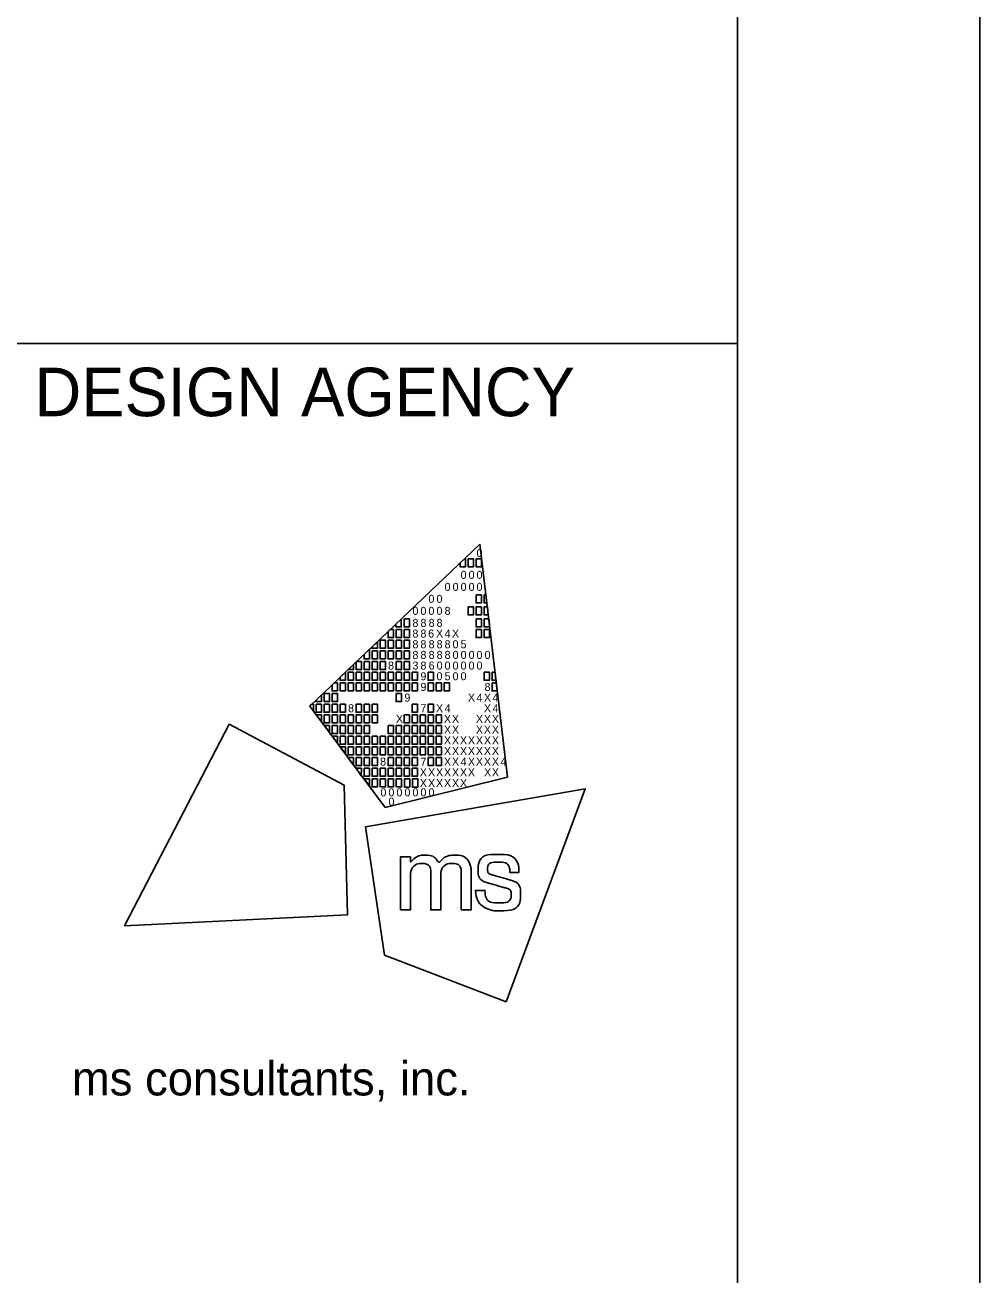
# Model space of a CAD drawing. Extents: x 0 to 34, y 0 to 22.
# Drawn here: x 32.03 to 34, y 2.578 to 5.157 of the extents above; entities that cross this region are included whole.
import ezdxf

# ---------------------------------------------------------------- set-up
doc = ezdxf.new("R2010")
doc.units = 0
for name, color, linetype in [('Default', 7, 'Continuous'), ('SH_Border', 7, 'Continuous'), ('SH_Cut_Line', 7, 'Continuous'), ('SH_Data', 7, 'Continuous')]:
    doc.layers.add(name, color=color, linetype=linetype)

msp = doc.modelspace()

# ---------------------------------------------------------------- linework, layer by layer
at = {"layer": 'Default'}
for p, q in [((32.6176, 3.7519), (32.9688, 4.0861)), ((32.9688, 4.0861), (32.9688, 4.0861)), ((32.9688, 4.0861), (33.0253, 3.6052)), ((32.773, 3.543), (32.6176, 3.7519)), ((33.0253, 3.6052), (32.773, 3.543))]:
    msp.add_line(p, q, dxfattribs=at)
for points in [[(32.9279, 4.0472), (32.9369, 4.0558), (32.939, 4.0558), (32.939, 4.0393), (32.9279, 4.0393)], [(32.9444, 4.0558), (32.9554, 4.0558), (32.9554, 4.0393), (32.9444, 4.0393)], [(32.9609, 4.0558), (32.9719, 4.0558), (32.9719, 4.0393), (32.9609, 4.0393)], [(32.9606, 3.9815), (32.9716, 3.9815), (32.9716, 3.965), (32.9606, 3.965)], [(32.9771, 3.9815), (32.9811, 3.9815), (32.983, 3.965), (32.9771, 3.965)], [(32.9442, 3.9567), (32.9552, 3.9567), (32.9552, 3.9402), (32.9442, 3.9402)], [(32.9606, 3.9567), (32.9716, 3.9567), (32.9716, 3.9402), (32.9606, 3.9402)], [(32.9771, 3.9567), (32.984, 3.9567), (32.9859, 3.9402), (32.9771, 3.9402)], [(32.7954, 3.9211), (32.8064, 3.9316), (32.8064, 3.9154), (32.7954, 3.9154)], [(32.8123, 3.9319), (32.8233, 3.9319), (32.8233, 3.9154), (32.8123, 3.9154)], [(32.9606, 3.9319), (32.9716, 3.9319), (32.9716, 3.9154), (32.9606, 3.9154)], [(32.9771, 3.9319), (32.9869, 3.9319), (32.9881, 3.9218), (32.9881, 3.9154), (32.9771, 3.9154)], [(32.7958, 3.9099), (32.8068, 3.9099), (32.8068, 3.8934), (32.7958, 3.8934)], [(32.8123, 3.9099), (32.8233, 3.9099), (32.8233, 3.8934), (32.8123, 3.8934)], [(32.9606, 3.9099), (32.9716, 3.9099), (32.9716, 3.8934), (32.9606, 3.8934)], [(32.9771, 3.9099), (32.9881, 3.9099), (32.9881, 3.8934), (32.9771, 3.8934)], [(32.7628, 3.8879), (32.7738, 3.8879), (32.7738, 3.8714), (32.7628, 3.8714)], [(32.7793, 3.8879), (32.7903, 3.8879), (32.7903, 3.8714), (32.7793, 3.8714)], [(32.7958, 3.8879), (32.8068, 3.8879), (32.8068, 3.8714), (32.7958, 3.8714)], [(32.8123, 3.8879), (32.8233, 3.8879), (32.8233, 3.8714), (32.8123, 3.8714)], [(32.7297, 3.8439), (32.7407, 3.8439), (32.7407, 3.8273), (32.7297, 3.8273)], [(32.7463, 3.8659), (32.7573, 3.8659), (32.7573, 3.8494), (32.7463, 3.8494)], [(32.7463, 3.8439), (32.7573, 3.8439), (32.7573, 3.8273), (32.7463, 3.8273)], [(32.7628, 3.8659), (32.7738, 3.8659), (32.7738, 3.8494), (32.7628, 3.8494)], [(32.7628, 3.8439), (32.7738, 3.8439), (32.7738, 3.8273), (32.7628, 3.8273)], [(32.7793, 3.8659), (32.7903, 3.8659), (32.7903, 3.8494), (32.7793, 3.8494)], [(32.7958, 3.8659), (32.8068, 3.8659), (32.8068, 3.8494), (32.7958, 3.8494)], [(32.7958, 3.8439), (32.8068, 3.8439), (32.8068, 3.8273), (32.7958, 3.8273)], [(32.8123, 3.8659), (32.8233, 3.8659), (32.8233, 3.8494), (32.8123, 3.8494)], [(32.8123, 3.8439), (32.8233, 3.8439), (32.8233, 3.8273), (32.8123, 3.8273)], [(32.6967, 3.8218), (32.7077, 3.8218), (32.7077, 3.8053), (32.6967, 3.8053)], [(32.7132, 3.8218), (32.7242, 3.8218), (32.7242, 3.8053), (32.7132, 3.8053)], [(32.7297, 3.8218), (32.7407, 3.8218), (32.7407, 3.8053), (32.7297, 3.8053)], [(32.7463, 3.8218), (32.7573, 3.8218), (32.7573, 3.8053), (32.7463, 3.8053)], [(32.7628, 3.8218), (32.7738, 3.8218), (32.7738, 3.8053), (32.7628, 3.8053)], [(32.7793, 3.8218), (32.7903, 3.8218), (32.7903, 3.8053), (32.7793, 3.8053)], [(32.7958, 3.8218), (32.8068, 3.8218), (32.8068, 3.8053), (32.7958, 3.8053)], [(32.8123, 3.8218), (32.8233, 3.8218), (32.8233, 3.8053), (32.8123, 3.8053)], [(32.8288, 3.8218), (32.8398, 3.8218), (32.8398, 3.8053), (32.8288, 3.8053)], [(32.8618, 3.8218), (32.8729, 3.8218), (32.8729, 3.8053), (32.8618, 3.8053)], [(32.9771, 3.8218), (32.9881, 3.8218), (32.9881, 3.8053), (32.9771, 3.8053)], [(32.9936, 3.8218), (32.9999, 3.8218), (33.0018, 3.8053), (32.9936, 3.8053)], [(32.6802, 3.7998), (32.6912, 3.7998), (32.6912, 3.7833), (32.6802, 3.7833)], [(32.6967, 3.7998), (32.7077, 3.7998), (32.7077, 3.7833), (32.6967, 3.7833)], [(32.7132, 3.7998), (32.7242, 3.7998), (32.7242, 3.7833), (32.7132, 3.7833)], [(32.7297, 3.7998), (32.7407, 3.7998), (32.7407, 3.7833), (32.7297, 3.7833)], [(32.7463, 3.7998), (32.7573, 3.7998), (32.7573, 3.7833), (32.7463, 3.7833)], [(32.7628, 3.7998), (32.7738, 3.7998), (32.7738, 3.7833), (32.7628, 3.7833)], [(32.7793, 3.7998), (32.7903, 3.7998), (32.7903, 3.7833), (32.7793, 3.7833)], [(32.7958, 3.7998), (32.8068, 3.7998), (32.8068, 3.7833), (32.7958, 3.7833)], [(32.8123, 3.7998), (32.8233, 3.7998), (32.8233, 3.7833), (32.8123, 3.7833)], [(32.8288, 3.7998), (32.8398, 3.7998), (32.8398, 3.7833), (32.8288, 3.7833)], [(32.8618, 3.7998), (32.8729, 3.7998), (32.8729, 3.7833), (32.8618, 3.7833)], [(32.8784, 3.7998), (32.8894, 3.7998), (32.8894, 3.7833), (32.8784, 3.7833)], [(32.8947, 3.7998), (32.9057, 3.7998), (32.9057, 3.7833), (32.8947, 3.7833)], [(32.9936, 3.7998), (33.0024, 3.7998), (33.0044, 3.7833), (32.9936, 3.7833)], [(32.6472, 3.7778), (32.6582, 3.7778), (32.6582, 3.7613), (32.6472, 3.7613)], [(32.6637, 3.7778), (32.6747, 3.7778), (32.6747, 3.7613), (32.6637, 3.7613)], [(32.7958, 3.7778), (32.8068, 3.7778), (32.8068, 3.7613), (32.7958, 3.7613)], [(32.6307, 3.7558), (32.6417, 3.7558), (32.6417, 3.7393), (32.6307, 3.7393)], [(32.6472, 3.7558), (32.6582, 3.7558), (32.6582, 3.7393), (32.6472, 3.7393)], [(32.6637, 3.7558), (32.6747, 3.7558), (32.6747, 3.7393), (32.6637, 3.7393)], [(32.6802, 3.7558), (32.6912, 3.7558), (32.6912, 3.7393), (32.6802, 3.7393)], [(32.7132, 3.7558), (32.7242, 3.7558), (32.7242, 3.7393), (32.7132, 3.7393)], [(32.7297, 3.7558), (32.7407, 3.7558), (32.7407, 3.7393), (32.7297, 3.7393)], [(32.7463, 3.7558), (32.7573, 3.7558), (32.7573, 3.7393), (32.7463, 3.7393)], [(32.8288, 3.7558), (32.8398, 3.7558), (32.8398, 3.7393), (32.8288, 3.7393)], [(32.8618, 3.7558), (32.8729, 3.7558), (32.8729, 3.7393), (32.8618, 3.7393)], [(32.6307, 3.7338), (32.6417, 3.7338), (32.6417, 3.72)], [(32.6472, 3.7338), (32.6582, 3.7338), (32.6582, 3.7173), (32.6472, 3.7173)], [(32.6637, 3.7338), (32.6747, 3.7338), (32.6747, 3.7173), (32.6637, 3.7173)], [(32.6802, 3.7338), (32.6912, 3.7338), (32.6912, 3.7173), (32.6802, 3.7173)], [(32.6967, 3.7338), (32.7077, 3.7338), (32.7077, 3.7173), (32.6967, 3.7173)], [(32.7132, 3.7338), (32.7242, 3.7338), (32.7242, 3.7173), (32.7132, 3.7173)], [(32.7297, 3.7338), (32.7407, 3.7338), (32.7407, 3.7173), (32.7297, 3.7173)], [(32.7463, 3.7338), (32.7573, 3.7338), (32.7573, 3.7173), (32.7463, 3.7173)], [(32.8123, 3.7338), (32.8233, 3.7338), (32.8233, 3.7173), (32.8123, 3.7173)], [(32.8288, 3.7338), (32.8398, 3.7338), (32.8398, 3.7173), (32.8288, 3.7173)], [(32.8453, 3.7338), (32.8563, 3.7338), (32.8563, 3.7173), (32.8453, 3.7173)], [(32.8618, 3.7338), (32.8729, 3.7338), (32.8729, 3.7173), (32.8618, 3.7173)], [(32.8784, 3.7338), (32.8894, 3.7338), (32.8894, 3.7173), (32.8784, 3.7173)], [(32.6472, 3.7117), (32.6582, 3.7117), (32.6582, 3.698)], [(32.6637, 3.7117), (32.6747, 3.7117), (32.6747, 3.6952), (32.6637, 3.6952)], [(32.6637, 3.6897), (32.6747, 3.6897), (32.6747, 3.676)], [(32.6747, 3.6897), (32.6747, 3.6897), (32.6747, 3.6897)], [(32.6802, 3.7117), (32.6912, 3.7117), (32.6912, 3.6952), (32.6802, 3.6952)], [(32.6802, 3.6897), (32.6912, 3.6897), (32.6912, 3.6732), (32.6802, 3.6732)], [(32.6967, 3.7117), (32.7077, 3.7117), (32.7077, 3.6952), (32.6967, 3.6952)], [(32.6967, 3.6897), (32.7077, 3.6897), (32.7077, 3.6732), (32.6967, 3.6732)], [(32.7132, 3.7117), (32.7242, 3.7117), (32.7242, 3.6952), (32.7132, 3.6952)], [(32.7132, 3.6897), (32.7242, 3.6897), (32.7242, 3.6732), (32.7132, 3.6732)], [(32.7297, 3.7117), (32.7407, 3.7117), (32.7407, 3.6952), (32.7297, 3.6952)], [(32.7297, 3.6897), (32.7407, 3.6897), (32.7407, 3.6732), (32.7297, 3.6732)], [(32.7463, 3.6897), (32.7573, 3.6897), (32.7573, 3.6732), (32.7463, 3.6732)], [(32.7628, 3.6897), (32.7738, 3.6897), (32.7738, 3.6732), (32.7628, 3.6732)], [(32.7793, 3.7117), (32.7903, 3.7117), (32.7903, 3.6952), (32.7793, 3.6952)], [(32.7793, 3.6897), (32.7903, 3.6897), (32.7903, 3.6732), (32.7793, 3.6732)], [(32.7958, 3.7117), (32.8068, 3.7117), (32.8068, 3.6952), (32.7958, 3.6952)], [(32.7958, 3.6897), (32.8068, 3.6897), (32.8068, 3.6732), (32.7958, 3.6732)], [(32.8123, 3.7117), (32.8233, 3.7117), (32.8233, 3.6952), (32.8123, 3.6952)], [(32.8123, 3.6897), (32.8233, 3.6897), (32.8233, 3.6732), (32.8123, 3.6732)], [(32.8288, 3.7117), (32.8398, 3.7117), (32.8398, 3.6952), (32.8288, 3.6952)], [(32.8288, 3.6897), (32.8398, 3.6897), (32.8398, 3.6732), (32.8288, 3.6732)], [(32.8453, 3.7117), (32.8563, 3.7117), (32.8563, 3.6952), (32.8453, 3.6952)], [(32.8453, 3.6897), (32.8563, 3.6897), (32.8563, 3.6732), (32.8453, 3.6732)], [(32.8618, 3.7117), (32.8729, 3.7117), (32.8729, 3.6952), (32.8618, 3.6952)], [(32.8618, 3.6897), (32.8729, 3.6897), (32.8729, 3.6732), (32.8618, 3.6732)], [(32.8784, 3.7117), (32.8894, 3.7117), (32.8894, 3.6952), (32.8784, 3.6952)], [(32.8784, 3.6897), (32.8894, 3.6897), (32.8894, 3.6732), (32.8784, 3.6732)], [(32.6802, 3.6677), (32.6912, 3.6677), (32.6912, 3.654)], [(32.6967, 3.6677), (32.7077, 3.6677), (32.7077, 3.6512), (32.6967, 3.6512)], [(32.7132, 3.6677), (32.7242, 3.6677), (32.7242, 3.6512), (32.7132, 3.6512)], [(32.7297, 3.6677), (32.7407, 3.6677), (32.7407, 3.6512), (32.7297, 3.6512)], [(32.7463, 3.6677), (32.7573, 3.6677), (32.7573, 3.6512), (32.7463, 3.6512)], [(32.7628, 3.6677), (32.7738, 3.6677), (32.7738, 3.6512), (32.7628, 3.6512)], [(32.7793, 3.6677), (32.7903, 3.6677), (32.7903, 3.6512), (32.7793, 3.6512)], [(32.7958, 3.6677), (32.8068, 3.6677), (32.8068, 3.6512), (32.7958, 3.6512)], [(32.8123, 3.6677), (32.8233, 3.6677), (32.8233, 3.6512), (32.8123, 3.6512)], [(32.8288, 3.6677), (32.8398, 3.6677), (32.8398, 3.6512), (32.8288, 3.6512)], [(32.8453, 3.6677), (32.8563, 3.6677), (32.8563, 3.6512), (32.8453, 3.6512)], [(32.8618, 3.6677), (32.8729, 3.6677), (32.8729, 3.6512), (32.8618, 3.6512)], [(32.8784, 3.6677), (32.8894, 3.6677), (32.8894, 3.6512), (32.8784, 3.6512)], [(32.7078, 3.6305), (32.6966, 3.6457), (32.7078, 3.6457)], [(32.7132, 3.6457), (32.7242, 3.6457), (32.7242, 3.6292), (32.7132, 3.6292)], [(32.7297, 3.6457), (32.7407, 3.6457), (32.7407, 3.6292), (32.7297, 3.6292)], [(32.7463, 3.6457), (32.7573, 3.6457), (32.7573, 3.6292), (32.7463, 3.6292)], [(32.7793, 3.6457), (32.7903, 3.6457), (32.7903, 3.6292), (32.7793, 3.6292)], [(32.7958, 3.6457), (32.8068, 3.6457), (32.8068, 3.6292), (32.7958, 3.6292)], [(32.8123, 3.6457), (32.8233, 3.6457), (32.8233, 3.6292), (32.8123, 3.6292)], [(32.8288, 3.6457), (32.8398, 3.6457), (32.8398, 3.6292), (32.8288, 3.6292)], [(32.8618, 3.6457), (32.8729, 3.6457), (32.8729, 3.6292), (32.8618, 3.6292)], [(32.8784, 3.6457), (32.8894, 3.6457), (32.8894, 3.6292), (32.8784, 3.6292)], [(32.724, 3.6082), (32.7132, 3.6237), (32.7242, 3.6237)], [(32.7297, 3.6237), (32.7407, 3.6237), (32.7407, 3.6072), (32.7297, 3.6072)], [(32.7463, 3.6237), (32.7573, 3.6237), (32.7573, 3.6072), (32.7463, 3.6072)], [(32.7628, 3.6237), (32.7738, 3.6237), (32.7738, 3.6072), (32.7628, 3.6072)], [(32.7793, 3.6237), (32.7903, 3.6237), (32.7903, 3.6072), (32.7793, 3.6072)], [(32.7958, 3.6237), (32.8068, 3.6237), (32.8068, 3.6072), (32.7958, 3.6072)], [(32.8123, 3.6237), (32.8233, 3.6237), (32.8233, 3.6072), (32.8123, 3.6072)], [(32.8288, 3.6237), (32.8398, 3.6237), (32.8398, 3.6072), (32.8288, 3.6072)], [(32.7302, 3.6017), (32.7407, 3.6017), (32.7408, 3.5875)], [(32.7463, 3.6017), (32.7573, 3.6017), (32.7573, 3.5852), (32.7463, 3.5852)], [(32.763, 3.6017), (32.774, 3.6017), (32.774, 3.5852), (32.763, 3.5852)], [(32.7794, 3.6017), (32.7904, 3.6017), (32.7904, 3.5852), (32.7794, 3.5852)], [(32.7961, 3.6017), (32.8071, 3.6017), (32.8071, 3.5852), (32.7961, 3.5852)], [(32.813, 3.6017), (32.824, 3.6017), (32.824, 3.5851), (32.813, 3.5851)], [(32.8296, 3.6017), (32.8407, 3.6017), (32.8407, 3.5851), (32.8296, 3.5851)]]:
    msp.add_lwpolyline(points, close=True, dxfattribs=at)
for points in [[(32.7903, 3.9099), (32.7836, 3.9099), (32.7793, 3.9058), (32.7793, 3.8934), (32.7903, 3.8934), (32.7903, 3.9099)], [(32.7407, 3.8691), (32.7297, 3.8587), (32.7297, 3.8494), (32.7407, 3.8494), (32.7407, 3.8691)], [(32.7573, 3.8849), (32.7463, 3.8744), (32.7463, 3.8714), (32.7573, 3.8714), (32.7573, 3.8849)], [(32.7242, 3.8439), (32.7142, 3.8439), (32.7132, 3.843), (32.7132, 3.8273), (32.7242, 3.8273), (32.7242, 3.8439)], [(32.6912, 3.822), (32.6802, 3.8115), (32.6802, 3.8053), (32.6912, 3.8053), (32.6912, 3.822)], [(32.7077, 3.8377), (32.6968, 3.8273), (32.7077, 3.8273), (32.7077, 3.8377)], [(32.6747, 3.7998), (32.6679, 3.7998), (32.6637, 3.7958), (32.6637, 3.7833), (32.6747, 3.7833), (32.6747, 3.7998)], [(32.6417, 3.7749), (32.6307, 3.7644), (32.6307, 3.7613), (32.6417, 3.7613), (32.6417, 3.7749)], [(32.6252, 3.7558), (32.6216, 3.7558), (32.6176, 3.7519), (32.6252, 3.7417), (32.6252, 3.7558)], [(32.4512, 3.7149), (32.2359, 3.2988), (32.6957, 3.3215), (32.6884, 3.5892), (32.4512, 3.7149)], [(33.0229, 3.1422), (33.1859, 3.5814), (32.7324, 3.5029), (32.7722, 3.2381), (33.0229, 3.1422)]]:
    msp.add_lwpolyline(points, dxfattribs=at)
for points in [[(32.8048, 3.3315), (32.8048, 3.3315), (32.8048, 3.4409), (32.8048, 3.4409), (32.8048, 3.4409), (32.8255, 3.4409), (32.8255, 3.4409), (32.8255, 3.4409), (32.8255, 3.4297), (32.8255, 3.4297), (32.8346, 3.4399), (32.8457, 3.4445), (32.8555, 3.4445), (32.8689, 3.4445), (32.8792, 3.4372), (32.8837, 3.4266), (32.8915, 3.4381), (32.905, 3.4446), (32.9166, 3.4446), (32.9325, 3.4446), (32.9451, 3.435), (32.9494, 3.4213), (32.9494, 3.4212), (32.9494, 3.4212), (32.9495, 3.4212), (32.9501, 3.419), (32.9507, 3.4172), (32.9507, 3.4071), (32.9507, 3.4071), (32.9507, 3.3314), (32.9507, 3.3314), (32.9507, 3.3314), (32.9303, 3.3314), (32.9303, 3.3314), (32.9303, 3.3314), (32.9303, 3.4048), (32.9303, 3.4048), (32.9303, 3.4201), (32.9219, 3.4274), (32.9111, 3.4274), (32.8995, 3.4274), (32.888, 3.4171), (32.888, 3.4001), (32.888, 3.4001), (32.888, 3.3315), (32.888, 3.3315), (32.888, 3.3315), (32.8674, 3.3315), (32.8674, 3.3315), (32.8674, 3.3315), (32.8674, 3.4059), (32.8674, 3.4059), (32.8674, 3.4203), (32.8588, 3.4274), (32.8497, 3.4274), (32.8384, 3.4274), (32.8254, 3.417), (32.8254, 3.3962), (32.8254, 3.3962), (32.8254, 3.3315), (32.8254, 3.3315), (32.8254, 3.3315), (32.8048, 3.3315), (32.8048, 3.3315)], [(32.9596, 3.3709), (32.9596, 3.3709), (32.9595, 3.3717), (32.9595, 3.3717), (32.9595, 3.3717), (32.9603, 3.3717), (32.9603, 3.3717), (32.9603, 3.3717), (32.9783, 3.3717), (32.9783, 3.3717), (32.9783, 3.3717), (32.9789, 3.3717), (32.9789, 3.3717), (32.9789, 3.3717), (32.979, 3.371), (32.979, 3.371), (32.9803, 3.3554), (32.9887, 3.346), (33.009, 3.346), (33.0273, 3.346), (33.0333, 3.3554), (33.0333, 3.3631), (33.0333, 3.3732), (33.0256, 3.3758), (33.0175, 3.378), (33.0175, 3.378), (32.987, 3.3867), (32.987, 3.3867), (32.9721, 3.3909), (32.9648, 3.4019), (32.9648, 3.4142), (32.9648, 3.4303), (32.9768, 3.4462), (33.0052, 3.4462), (33.0348, 3.4462), (33.0489, 3.4285), (33.0489, 3.4095), (33.0489, 3.4095), (33.0489, 3.4087), (33.0489, 3.4087), (33.0489, 3.4087), (33.0482, 3.4087), (33.0482, 3.4087), (33.0482, 3.4087), (33.0312, 3.4087), (33.0312, 3.4087), (33.0312, 3.4087), (33.0305, 3.4087), (33.0305, 3.4087), (33.0305, 3.4087), (33.0305, 3.4094), (33.0305, 3.4094), (33.0302, 3.4208), (33.0227, 3.43), (33.0056, 3.43), (32.9891, 3.43), (32.9843, 3.4218), (32.9843, 3.4157), (32.9843, 3.4108), (32.9869, 3.4059), (32.9959, 3.4033), (32.9959, 3.4033), (33.0255, 3.3948), (33.0255, 3.3948), (33.0462, 3.3889), (33.0527, 3.3777), (33.0527, 3.3639), (33.0527, 3.3462), (33.041, 3.3298), (33.0087, 3.3298), (32.9952, 3.3298), (32.9877, 3.3321), (32.9823, 3.3348), (32.9691, 3.3414), (32.961, 3.3536), (32.9596, 3.3709)]]:
    msp.add_open_spline(points, degree=3, dxfattribs=at)
at = {"layer": 'SH_Border'}
msp.add_line((32, 4.5), (33.5, 4.5), dxfattribs=at)
msp.add_lwpolyline([(1.5, 21.5), (33.5, 21.5), (33.5, 0.5), (1.5, 0.5)], close=True, dxfattribs=at)
at = {"layer": 'SH_Cut_Line'}
msp.add_lwpolyline([(0, 0), (34, 0), (34, 22), (0, 22)], close=True, dxfattribs=at)
at = {"layer": 'SH_Data'}
msp.add_line((32.75, 3.5), (32.75, 3.5), dxfattribs=at)

# ---------------------------------------------------------------- texts
at = {"layer": 'Default'}
for s, p in [('0', (32.9617, 4.0597)), ('0', (32.9288, 4.0145)), ('0', (32.9453, 4.0145)), ('0', (32.9617, 4.0145)), ('0', (32.8958, 3.9897)), ('0', (32.9123, 3.9897)), ('0', (32.9288, 3.9897)), ('0', (32.9453, 3.9897)), ('0', (32.9617, 3.9897)), ('0', (32.8625, 3.965)), ('0', (32.8791, 3.965)), ('0', (32.8295, 3.9402)), ('0', (32.846, 3.9402)), ('0', (32.8625, 3.9402)), ('0', (32.8791, 3.9402)), ('8', (32.8958, 3.9402)), ('8', (32.8295, 3.9154)), ('8', (32.846, 3.9154)), ('8', (32.8629, 3.9154)), ('8', (32.8793, 3.9154)), ('8', (32.8295, 3.8934)), ('8', (32.846, 3.8934)), ('6', (32.8618, 3.8934)), ('X', (32.8781, 3.8934)), ('4', (32.8959, 3.8934)), ('X', (32.911, 3.8934)), ('8', (32.8295, 3.8713)), ('8', (32.846, 3.8713)), ('8', (32.8629, 3.8713)), ('8', (32.8794, 3.8713)), ('8', (32.8958, 3.8713)), ('0', (32.9123, 3.8713)), ('5', (32.9287, 3.8713)), ('8', (32.7793, 3.8273)), ('8', (32.8295, 3.8494)), ('3', (32.8295, 3.8273)), ('8', (32.846, 3.8494)), ('8', (32.846, 3.8273)), ('8', (32.8629, 3.8494)), ('6', (32.8629, 3.8273)), ('0', (32.8794, 3.8273)), ('8', (32.8794, 3.8494)), ('0', (32.8958, 3.8273)), ('8', (32.8958, 3.8494)), ('0', (32.9123, 3.8494)), ('0', (32.9123, 3.8273)), ('0', (32.9288, 3.8494)), ('0', (32.9288, 3.8273)), ('0', (32.9453, 3.8494)), ('0', (32.9453, 3.8273)), ('0', (32.9617, 3.8494)), ('0', (32.9617, 3.8273)), ('0', (32.9782, 3.8494)), ('9', (32.846, 3.8053)), ('0', (32.8791, 3.8053)), ('5', (32.8958, 3.8053)), ('0', (32.9123, 3.8053)), ('0', (32.9288, 3.8053)), ('9', (32.846, 3.7833)), ('8', (32.9782, 3.7833)), ('9', (32.813, 3.7613)), ('X', (32.9439, 3.7613)), ('4', (32.9617, 3.7613)), ('X', (32.9769, 3.7613)), ('4', (32.9947, 3.7613)), ('8', (32.6967, 3.7393)), ('7', (32.846, 3.7393)), ('X', (32.8781, 3.7393)), ('4', (32.8959, 3.7393)), ('X', (32.9769, 3.7393)), ('4', (32.9947, 3.7393)), ('X', (32.7955, 3.7173)), ('X', (32.8945, 3.7173)), ('X', (32.911, 3.7173)), ('X', (32.9604, 3.7173)), ('X', (32.9769, 3.7173)), ('X', (32.9934, 3.7173)), ('X', (32.8945, 3.6952)), ('X', (32.8945, 3.6732)), ('X', (32.911, 3.6952)), ('X', (32.911, 3.6732)), ('X', (32.9275, 3.6732)), ('X', (32.9439, 3.6732)), ('X', (32.9604, 3.6952)), ('X', (32.9604, 3.6732)), ('X', (32.9769, 3.6952)), ('X', (32.9769, 3.6732)), ('X', (32.9934, 3.6952)), ('X', (32.9934, 3.6732)), ('X', (32.8945, 3.6512)), ('X', (32.911, 3.6512)), ('X', (32.9275, 3.6512)), ('X', (32.9439, 3.6512)), ('X', (32.9604, 3.6512)), ('X', (32.9769, 3.6512)), ('X', (32.9934, 3.6512)), ('8', (32.7628, 3.6292)), ('7', (32.846, 3.6292)), ('X', (32.8945, 3.6292)), ('X', (32.911, 3.6292)), ('4', (32.9288, 3.6292)), ('X', (32.9439, 3.6292)), ('X', (32.9604, 3.6292)), ('X', (32.9769, 3.6292)), ('X', (32.9934, 3.6292)), ('4', (33.0112, 3.6292)), ('X', (32.8447, 3.6072)), ('X', (32.8616, 3.6072)), ('X', (32.8781, 3.6072)), ('X', (32.8945, 3.6072)), ('X', (32.911, 3.6072)), ('X', (32.9275, 3.6072)), ('X', (32.9439, 3.6072)), ('X', (32.9772, 3.6072)), ('X', (32.9934, 3.6072)), ('X', (32.8447, 3.5851)), ('X', (32.8616, 3.5851)), ('X', (32.8781, 3.5851)), ('X', (32.8945, 3.5851)), ('X', (32.911, 3.5851)), ('X', (32.9275, 3.5851)), ('0', (32.7635, 3.5659)), ('0', (32.78, 3.5659)), ('0', (32.78, 3.5467)), ('0', (32.7965, 3.5659)), ('0', (32.813, 3.5659)), ('0', (32.8295, 3.5659)), ('0', (32.846, 3.5659)), ('0', (32.8625, 3.5659))]:
    msp.add_text(s, height=0.0165, rotation=360, dxfattribs=at).set_placement(p)
at = {"layer": 'SH_Border'}
msp.add_text('ms consultants, inc.', height=0.07, rotation=360, dxfattribs=at).set_placement((32.1273, 2.9489))
at = {"layer": 'SH_Data'}
msp.add_text('DESIGN AGENCY', height=0.1, dxfattribs=at).set_placement((32.05, 4.35))

doc.saveas('drawing.dxf')
